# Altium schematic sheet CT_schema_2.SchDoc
size 366 x 279 mm
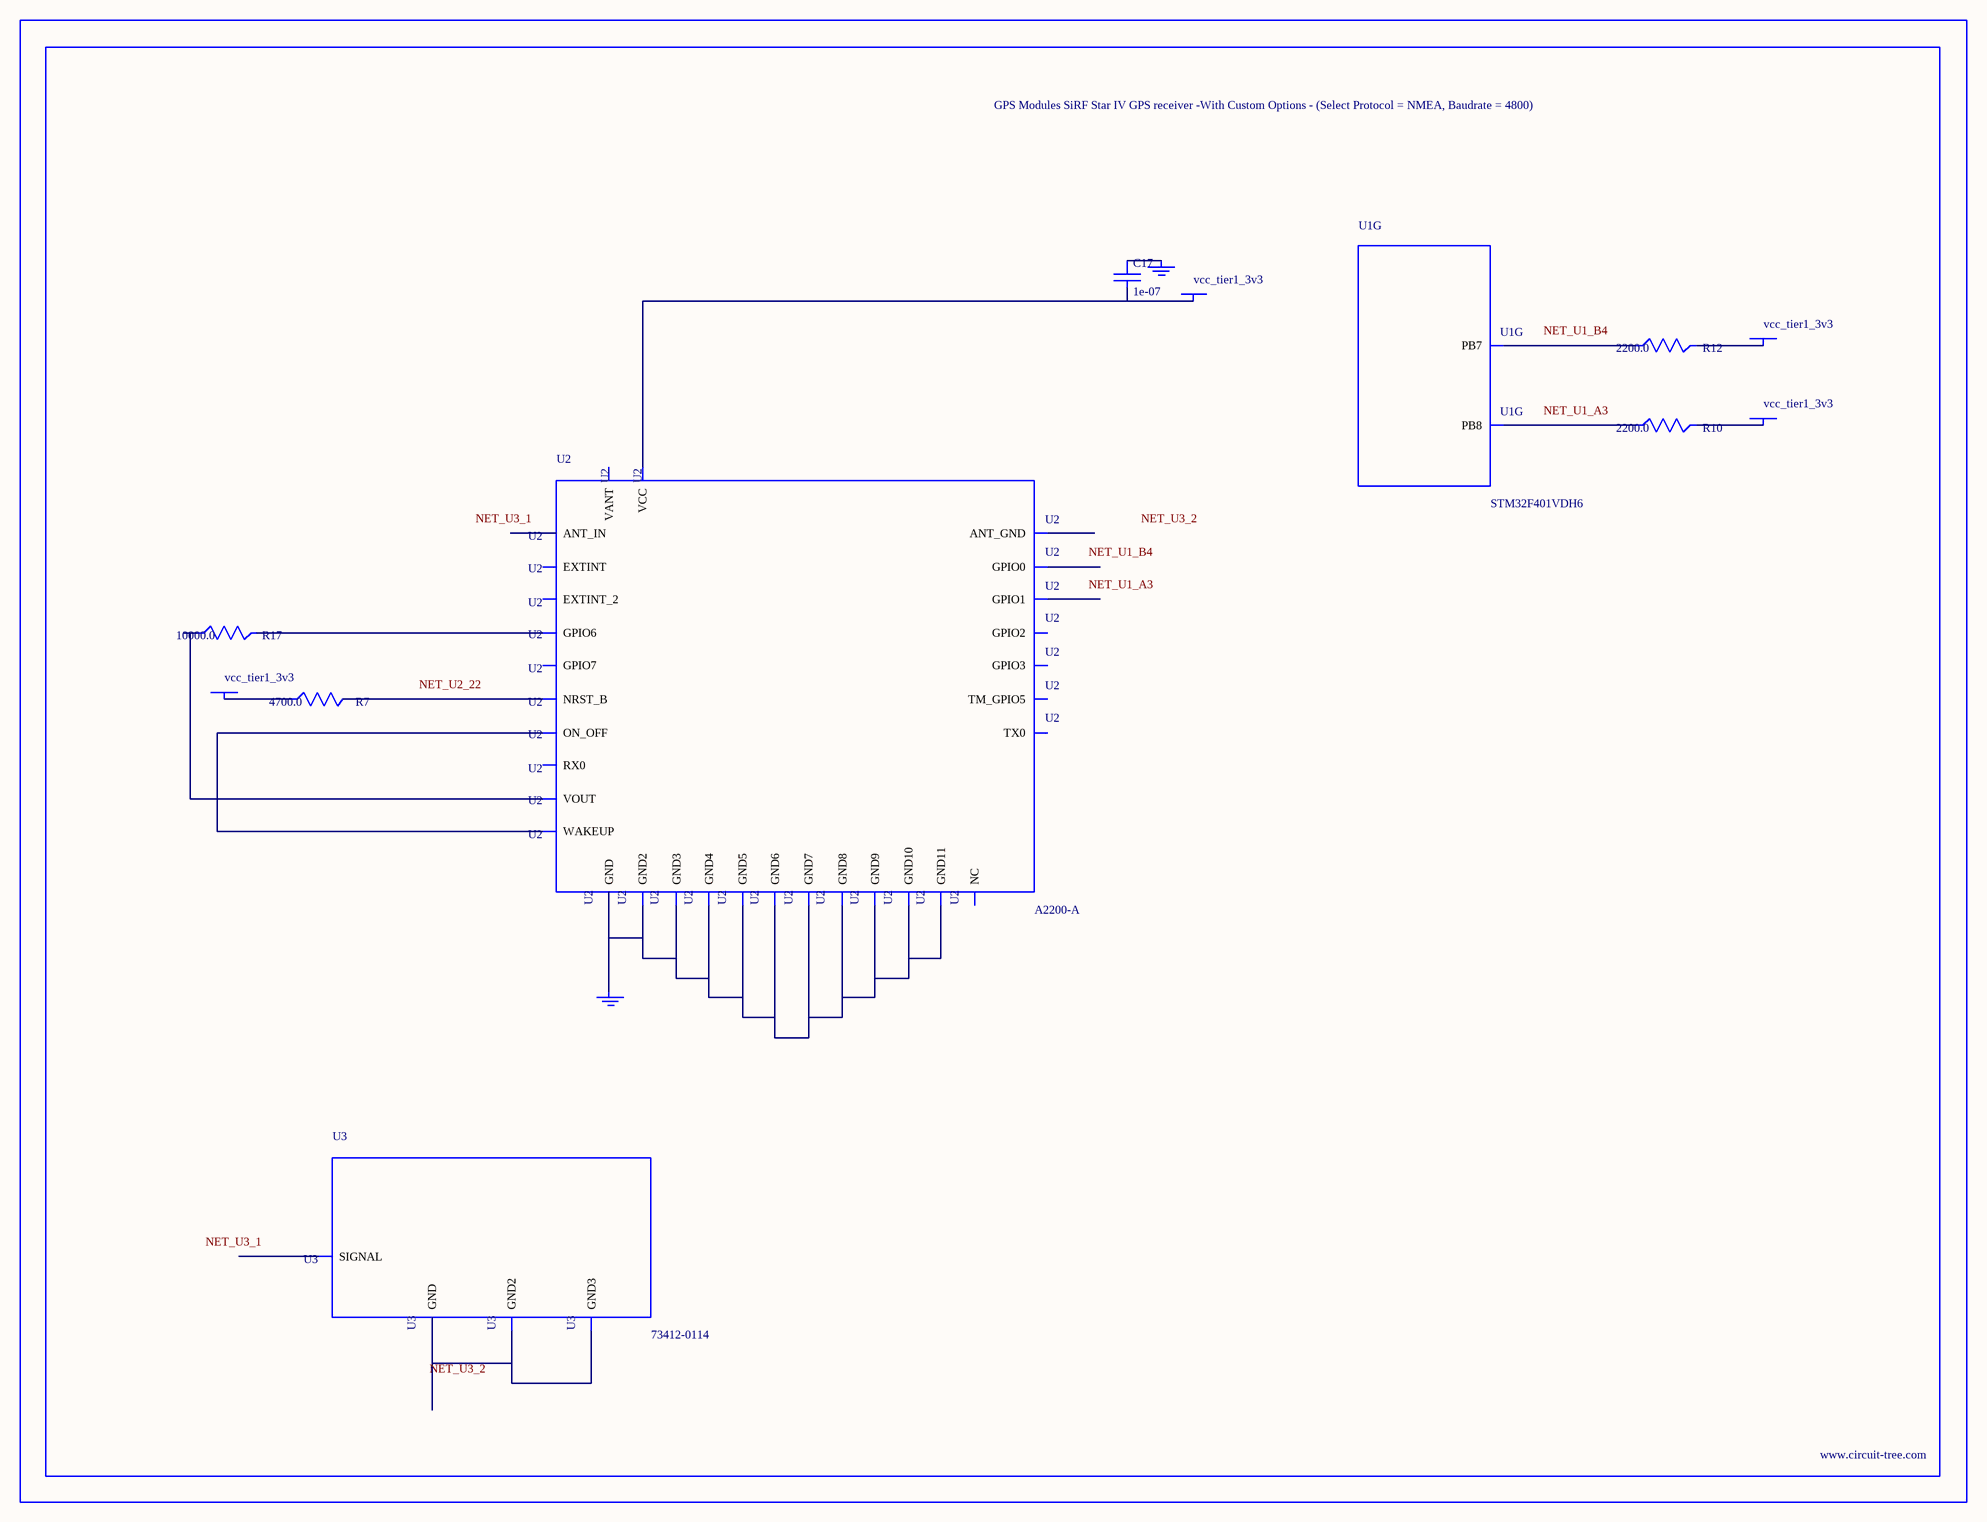
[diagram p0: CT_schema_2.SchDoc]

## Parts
BORDER1  (no value)
C17  1e-07  [C0402]
GND_INSTANCE_1_0  (no value)
GND_INSTANCE_1_1  (no value)
POWER_INSTANCE_1_0  vcc_tier1_3v3
POWER_INSTANCE_1_1  vcc_tier1_3v3
POWER_INSTANCE_1_2  vcc_tier1_3v3
POWER_INSTANCE_1_3  vcc_tier1_3v3
R7  4700.0  [R0603]
R10  2200.0  [R0603]
R12  2200.0  [R0603]
R17  10000.0  [R0603]
U1  STM32F401VDH6  [UFBGA100]  (part G of 10)
U2  A2200-A  [A2200-A]
U3  73412-0114  [COAXIAL_C]

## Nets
NetC17_1: C17.1 GND_INSTANCE_1_0.0(GND)
NetC17_2: C17.2 POWER_INSTANCE_1_0.0(PWR) U2.20(VCC)
NetGND_INSTANCE_1_1_0: GND_INSTANCE_1_1.0(GND) U2.7(GND) U2.8(GND2) U2.23(GND3) U2.24(GND4) U2.25(GND5) U2.26(GND6) U2.27(GND7) U2.28(GND8) U2.29(GND9) U2.30(GND10) U2.31(GND11)
NetPOWER_INSTANCE_1_1_0: POWER_INSTANCE_1_1.0(PWR) R7.1
NetPOWER_INSTANCE_1_2_0: POWER_INSTANCE_1_2.0(PWR) R12.2
NetPOWER_INSTANCE_1_3_0: POWER_INSTANCE_1_3.0(PWR) R10.2
NetR7_2: R7.2 U2.22(NRST_B)
NetR10_1: R10.1 U1.A3(PB8)
NetR12_1: R12.1 U1.B4(PB7)
NetR17_1: R17.1 U2.2(VOUT)
NetR17_2: R17.2 U2.17(GPIO6)
NetU2_6: U2.6(ON_OFF) U2.19(WAKEUP)
NetU3_2: U3.2(GND) U3.3(GND2) U3.4(GND3)

Not connected (* = marked no-connect by the designer): U2 1(GPIO2) 3(TX0) 4(RX0) 5(EXTINT_2) 9(VANT) 10(ANT_GND) 11(ANT_IN) 12(GPIO3) 13(EXTINT) 14(TM_GPIO5) 15(GPIO1) 16(GPIO0) 18(GPIO7) 21(NC); U3 1(SIGNAL)

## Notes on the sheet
- Labels drawn without touching a wire or pin: NET_U1_A3, NET_U1_B4, NET_U2_22, NET_U3_1, NET_U3_2

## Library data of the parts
BORDER1 = BORDER_PAGE1
C17 = C0402C104K3RACTU
GND_INSTANCE_1_0 GND_INSTANCE_1_1 = GND
POWER_INSTANCE_1_0-POWER_INSTANCE_1_3 = PWR
R7 = RC0603JR-074K7L
R10 R12 = RC0603JR-072K2L
R17 = RC0603JR-0710KL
